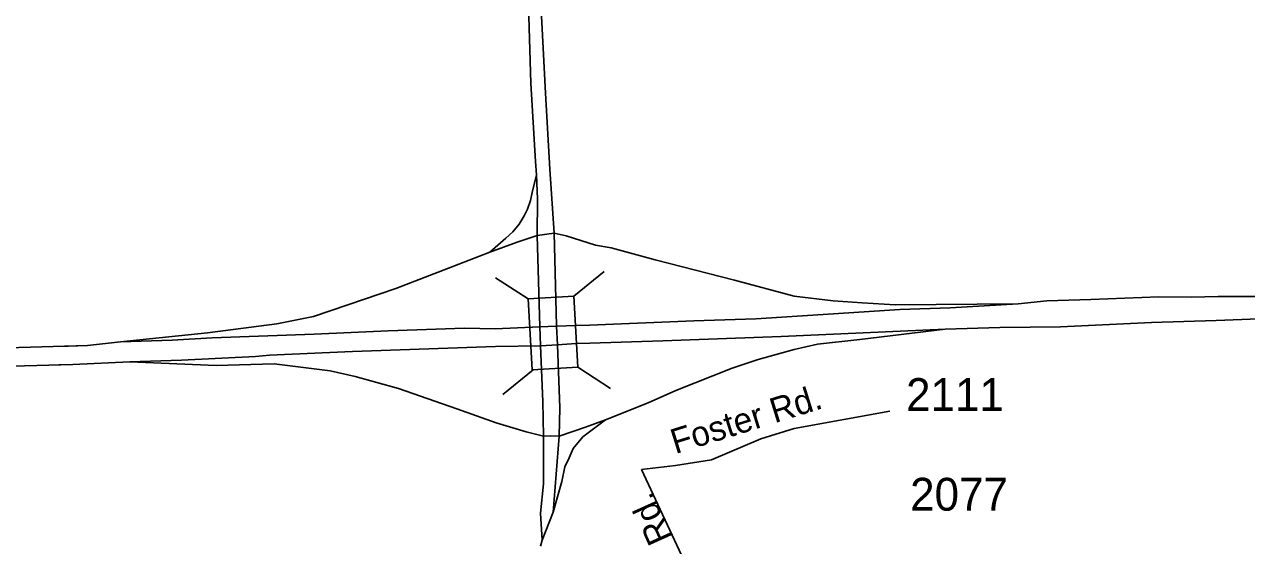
# Model space of a CAD drawing. Extents: x 1364363 to 1407445, y 538563 to 573342.
# Drawn here: x 1392969 to 1397619, y 553876 to 555859 of the extents above; entities that cross this region are included whole.
import ezdxf

# ---------------------------------------------------------------- set-up
doc = ezdxf.new("R2010")
doc.units = 0
for name, color, linetype in [('Exist Road Primary Interstate Divided Center Attributed', 7, 'Continuous'), ('Exist Road Primary Interstate Ramp 1 Lane Attributed', 7, 'Continuous'), ('Exist Road Primary NC Attributed', 7, 'Continuous'), ('Exist Road Primary NC Divided Attributed', 7, 'Continuous'), ('Exist Road Primary NC Structure Standard Bridge CELL', 7, 'Continuous'), ('Exist Road Secondary Type 51 Attributed', 7, 'Continuous'), ('Exist Road Secondary Type 51 Label', 7, 'Continuous'), ('Exist Road Secondary Type 51 Number Label', 7, 'Continuous')]:
    doc.layers.add(name, color=color, linetype=linetype)

msp = doc.modelspace()

# ---------------------------------------------------------------- linework, layer by layer
at = {"layer": 'Exist Road Primary Interstate Divided Center Attributed'}
for points in [[(1393334.1, 554650.6), (1393208.8, 554636.6), (1392904.1, 554627.7), (1392654.8, 554617.2), (1392079.2, 554588.8), (1391717.5, 554575.4), (1391295.9, 554565), (1391159.1, 554570.5), (1391050.8, 554573.9), (1390956.2, 554582), (1390800.3, 554606.6), (1390596.7, 554648.1), (1390451, 554686.9), (1390252.5, 554747.1), (1390046.2, 554841.3), (1389929.6, 554904)], [(1398849.6, 554881.8), (1398622.7, 554863.5), (1398365.7, 554860.9), (1398224.1, 554853.5), (1397774.1, 554823.3), (1397511, 554823.3), (1397410.2, 554820.3), (1397285.4, 554822.5), (1397027.4, 554812.3), (1396859.2, 554806.8), (1396750.2, 554795.2)], [(1398849.6, 554881.8), (1398622.7, 554863.5), (1398365.7, 554860.9), (1398224.1, 554853.5), (1397774.1, 554823.3), (1397511, 554823.3), (1397410.2, 554820.3), (1397285.4, 554822.5), (1397027.4, 554812.3), (1396859.2, 554806.8), (1396750.2, 554795.2)], [(1389950.7, 554820.1), (1390107.1, 554752.5), (1390152.2, 554734.9), (1390279.4, 554676.9), (1390414.8, 554627.7), (1390541, 554585.9), (1390641, 554563.5), (1390764.2, 554535.1), (1390924.2, 554508.2), (1391099.7, 554491.8), (1391285.9, 554488.8), (1391495.9, 554494.8), (1391787.6, 554511.9), (1392073.5, 554525), (1392329.8, 554531.6), (1392830.9, 554556.2), (1393152.9, 554564.5), (1393369.8, 554575.1)], [(1396472.2, 554699.3), (1396679.9, 554705.3), (1396910.8, 554708.3), (1397203.9, 554721.7), (1397257.8, 554724.7), (1397504, 554732.2), (1397924.9, 554748.6), (1398253, 554772.1), (1398871.8, 554808)], [(1396472.2, 554699.3), (1396679.9, 554705.3), (1396910.8, 554708.3), (1397203.9, 554721.7), (1397257.8, 554724.7), (1397504, 554732.2), (1397924.9, 554748.6), (1398253, 554772.1), (1398871.8, 554808)], [(1396750.2, 554795.2), (1396491.5, 554780.3), (1396300.1, 554774.1), (1396008.2, 554754.6), (1395752.7, 554738.1), (1395515.7, 554730.7), (1395119.8, 554714.9), (1395067.1, 554712.8), (1394994.2, 554710.5)], [(1396750.2, 554795.2), (1396491.5, 554780.3), (1396300.1, 554774.1), (1396008.2, 554754.6), (1395752.7, 554738.1), (1395515.7, 554730.7), (1395119.8, 554714.9), (1395067.1, 554712.8), (1394994.2, 554710.5)], [(1394929.9, 554708.5), (1394759.8, 554700.9), (1394644.1, 554702.6), (1394353.4, 554693.1), (1394071.4, 554680.1), (1393683.3, 554665.8), (1393530.8, 554657.6), (1393334.1, 554650.6)], [(1394929.9, 554708.5), (1394759.8, 554700.9), (1394644.1, 554702.6), (1394353.4, 554693.1), (1394071.4, 554680.1), (1393683.3, 554665.8), (1393530.8, 554657.6), (1393334.1, 554650.6)], [(1394994.2, 554710.5), (1394929.9, 554708.5)], [(1394994.2, 554710.5), (1394929.9, 554708.5)], [(1394997.1, 554640), (1395068.6, 554644.1), (1395121, 554645.8), (1395398, 554654.5), (1395848.9, 554671), (1396472.2, 554699.3)], [(1394997.1, 554640), (1395068.6, 554644.1), (1395121, 554645.8), (1395398, 554654.5), (1395848.9, 554671), (1396472.2, 554699.3)], [(1393334.1, 554650.6), (1393208.8, 554636.6), (1393099.7, 554633.4)], [(1393369.8, 554575.1), (1393566.9, 554580.9), (1393847.9, 554595.7), (1393901.6, 554599.8), (1394217.8, 554614.7), (1394761.4, 554633.5), (1394932.8, 554636.3)], [(1393369.8, 554575.1), (1393566.9, 554580.9), (1393847.9, 554595.7), (1393901.6, 554599.8), (1394217.8, 554614.7), (1394761.4, 554633.5), (1394932.8, 554636.3)], [(1394932.8, 554636.3), (1394997.1, 554640)], [(1394932.8, 554636.3), (1394997.1, 554640)], [(1393099.7, 554563.1), (1393152.9, 554564.5), (1393369.8, 554575.1)]]:
    msp.add_lwpolyline(points, dxfattribs=at)
at = {"layer": 'Exist Road Primary Interstate Ramp 1 Lane Attributed'}
for points in [[(1394917.5, 555286.5), (1394901.5, 555219.7), (1394894.3, 555188.9), (1394883.2, 555155.6), (1394870.7, 555130.1), (1394851.4, 555098.7), (1394827.3, 555069.8), (1394800.3, 555045.2), (1394739.5, 554992.2)], [(1394917.5, 555286.5), (1394901.5, 555219.7), (1394894.3, 555188.9), (1394883.2, 555155.6), (1394870.7, 555130.1), (1394851.4, 555098.7), (1394827.3, 555069.8), (1394800.3, 555045.2), (1394739.5, 554992.2)], [(1394920.3, 555056), (1394844.1, 555029.8), (1394739.5, 554992.2)], [(1394920.3, 555056), (1394844.1, 555029.8), (1394739.5, 554992.2)], [(1394984.7, 555064.2), (1394920.3, 555056)], [(1394984.7, 555064.2), (1394920.3, 555056)], [(1396750.2, 554795.2), (1396282.4, 554791.2), (1396157.1, 554799.3), (1396046.8, 554806.8), (1395898.3, 554825.1), (1395671.3, 554885.2), (1395368.6, 554962.8), (1395201.8, 555008.4), (1395142.5, 555019.3), (1395030.1, 555054.5), (1394984.7, 555064.2)], [(1396750.2, 554795.2), (1396282.4, 554791.2), (1396157.1, 554799.3), (1396046.8, 554806.8), (1395898.3, 554825.1), (1395671.3, 554885.2), (1395368.6, 554962.8), (1395201.8, 555008.4), (1395142.5, 555019.3), (1395030.1, 555054.5), (1394984.7, 555064.2)], [(1394739.5, 554992.2), (1394582.8, 554930.8), (1394382.6, 554853.8), (1394199.5, 554791.7), (1394068.5, 554747.5), (1393929.1, 554719.2), (1393666.3, 554684.9), (1393334.1, 554650.6)], [(1394739.5, 554992.2), (1394582.8, 554930.8), (1394382.6, 554853.8), (1394199.5, 554791.7), (1394068.5, 554747.5), (1393929.1, 554719.2), (1393666.3, 554684.9), (1393334.1, 554650.6)], [(1396472.2, 554699.3), (1396147.6, 554659.5), (1395986.2, 554642), (1395898.4, 554622.2), (1395761.5, 554584.1), (1395662.1, 554550.7), (1395448.3, 554466.2), (1395342.7, 554418.6), (1395180.4, 554354)], [(1396472.2, 554699.3), (1396147.6, 554659.5), (1395986.2, 554642), (1395898.4, 554622.2), (1395761.5, 554584.1), (1395662.1, 554550.7), (1395448.3, 554466.2), (1395342.7, 554418.6), (1395180.4, 554354)], [(1393369.8, 554575.1), (1393698.8, 554561.4), (1393919.5, 554566.9), (1394131.9, 554540.9), (1394227.9, 554518.9), (1394392.1, 554474), (1394614.3, 554396.3), (1394763.7, 554343), (1394878.6, 554308), (1394944.6, 554292.3)], [(1393369.8, 554575.1), (1393698.8, 554561.4), (1393919.5, 554566.9), (1394131.9, 554540.9), (1394227.9, 554518.9), (1394392.1, 554474), (1394614.3, 554396.3), (1394763.7, 554343), (1394878.6, 554308), (1394944.6, 554292.3)], [(1394981.6, 554002.8), (1395014.5, 554119.4), (1395025.4, 554175.4), (1395041.8, 554210.1), (1395057, 554245.6), (1395094.1, 554289.5), (1395180.4, 554354)], [(1394981.6, 554002.8), (1395014.5, 554119.4), (1395025.4, 554175.4), (1395041.8, 554210.1), (1395057, 554245.6), (1395094.1, 554289.5), (1395180.4, 554354)], [(1395003.6, 554292.3), (1395103.9, 554326.3), (1395180.4, 554354)], [(1395003.6, 554292.3), (1395103.9, 554326.3), (1395180.4, 554354)], [(1394944.6, 554292.3), (1394970.7, 554293.6), (1395003.6, 554292.3)], [(1394944.6, 554292.3), (1394970.7, 554293.6), (1395003.6, 554292.3)]]:
    msp.add_lwpolyline(points, dxfattribs=at)
at = {"layer": 'Exist Road Primary NC Attributed'}
msp.add_lwpolyline([(1394932.4, 553873.7), (1394939.6, 553896.5)], dxfattribs=at)
msp.add_lwpolyline([(1394932.4, 553873.7), (1394939.6, 553896.5)], dxfattribs=at)
at = {"layer": 'Exist Road Primary NC Divided Attributed'}
msp.add_line((1394997.1, 554640), (1394994.2, 554710.5), dxfattribs=at)
msp.add_line((1394997.1, 554640), (1394994.2, 554710.5), dxfattribs=at)
for points in [[(1395047.9, 559619.8), (1395020, 559494.5), (1394962.8, 559261.6), (1394883.8, 558946.9), (1394756.5, 558444.8), (1394733.8, 558324.4), (1394731.8, 558313), (1394712.9, 558171.7), (1394701.3, 558051.8), (1394699.3, 558002.1), (1394695.2, 557919.7), (1394695.2, 557805.9), (1394702.7, 557583.9), (1394710.8, 557502.8), (1394725.1, 557353), (1394755.8, 557087.5), (1394778.9, 556872.5), (1394812.8, 556641), (1394846.6, 556384.2), (1394865.9, 556194.6), (1394887.4, 555930.4), (1394895.9, 555634.7), (1394913.4, 555337.2), (1394917.5, 555286.5)], [(1395047.9, 559619.8), (1395020, 559494.5), (1394962.8, 559261.6), (1394883.8, 558946.9), (1394756.5, 558444.8), (1394733.8, 558324.4), (1394731.8, 558313), (1394712.9, 558171.7), (1394701.3, 558051.8), (1394699.3, 558002.1), (1394695.2, 557919.7), (1394695.2, 557805.9), (1394702.7, 557583.9), (1394710.8, 557502.8), (1394725.1, 557353), (1394755.8, 557087.5), (1394778.9, 556872.5), (1394812.8, 556641), (1394846.6, 556384.2), (1394865.9, 556194.6), (1394887.4, 555930.4), (1394895.9, 555634.7), (1394913.4, 555337.2), (1394917.5, 555286.5)], [(1394984.7, 555064.2), (1394968.2, 555307.8), (1394951.3, 555597.1), (1394951.3, 555597.4), (1394934.4, 555939.3), (1394923.6, 556093.1), (1394897.4, 556340.9), (1394879.7, 556533.5), (1394847.4, 556778.4), (1394800.5, 557126.3), (1394755.1, 557433.3), (1394742.8, 557538.4), (1394732, 557728), (1394733.3, 557888.3), (1394740.5, 558016.1), (1394746.6, 558131.1), (1394762, 558256.5), (1394805.9, 558474.5), (1394841.3, 558667.1), (1394897.4, 558883.6), (1394957.4, 559118), (1395087.5, 559625.6)], [(1394984.7, 555064.2), (1394968.2, 555307.8), (1394951.3, 555597.1), (1394951.3, 555597.4), (1394934.4, 555939.3), (1394923.6, 556093.1), (1394897.4, 556340.9), (1394879.7, 556533.5), (1394847.4, 556778.4), (1394800.5, 557126.3), (1394755.1, 557433.3), (1394742.8, 557538.4), (1394732, 557728), (1394733.3, 557888.3), (1394740.5, 558016.1), (1394746.6, 558131.1), (1394762, 558256.5), (1394805.9, 558474.5), (1394841.3, 558667.1), (1394897.4, 558883.6), (1394957.4, 559118), (1395087.5, 559625.6)], [(1394917.5, 555286.5), (1394921.7, 555193.2), (1394920.3, 555056)], [(1394917.5, 555286.5), (1394921.7, 555193.2), (1394920.3, 555056)], [(1394920.3, 555056), (1394929.9, 554708.5)], [(1394920.3, 555056), (1394929.9, 554708.5)], [(1394994.2, 554710.5), (1394992.1, 554764.3), (1394984.7, 555064.2)], [(1394994.2, 554710.5), (1394992.1, 554764.3), (1394984.7, 555064.2)], [(1394929.9, 554708.5), (1394931.3, 554673.2), (1394932.8, 554636.3)], [(1394929.9, 554708.5), (1394931.3, 554673.2), (1394932.8, 554636.3)], [(1394932.8, 554636.3), (1394941.3, 554423.9), (1394944.6, 554292.3)], [(1394932.8, 554636.3), (1394941.3, 554423.9), (1394944.6, 554292.3)], [(1395003.6, 554292.3), (1395006.7, 554400), (1394997.1, 554640)], [(1395003.6, 554292.3), (1395006.7, 554400), (1394997.1, 554640)], [(1394944.6, 554292.3), (1394944.6, 554111.2), (1394932.3, 553998.7), (1394939.6, 553896.5)], [(1394944.6, 554292.3), (1394944.6, 554111.2), (1394932.3, 553998.7), (1394939.6, 553896.5)], [(1394981.6, 554002.8), (1395003.6, 554292.3)], [(1394981.6, 554002.8), (1395003.6, 554292.3)], [(1394939.6, 553896.5), (1394981.6, 554002.8)], [(1394939.6, 553896.5), (1394981.6, 554002.8)]]:
    msp.add_lwpolyline(points, dxfattribs=at)
at = {"layer": 'Exist Road Primary NC Structure Standard Bridge CELL'}
for p, q in [((1395174.7, 554917.9), (1395059.8, 554824.1)), ((1395174.7, 554917.9), (1395059.8, 554824.1)), ((1394761.6, 554894.5), (1394886.3, 554814.2)), ((1394761.6, 554894.5), (1394886.3, 554814.2)), ((1394904.7, 554544.7), (1394789.8, 554450.8)), ((1394904.7, 554544.7), (1394789.8, 554450.8)), ((1395074.2, 554554.3), (1395199, 554474)), ((1395074.2, 554554.3), (1395199, 554474))]:
    msp.add_line(p, q, dxfattribs=at)
msp.add_lwpolyline([(1395059.8, 554824.1), (1395075, 554554.4), (1394901.6, 554544.5), (1394886.3, 554814.2)], close=True, dxfattribs=at)
msp.add_lwpolyline([(1395059.8, 554824.1), (1395075, 554554.4), (1394901.6, 554544.5), (1394886.3, 554814.2)], close=True, dxfattribs=at)
at = {"layer": 'Exist Road Secondary Type 51 Attributed'}
for points in [[(1395316.5, 554165.1), (1395446.9, 554180.2), (1395583.4, 554201.5), (1395771.3, 554281.6), (1395898.1, 554321), (1396261.6, 554387.5)], [(1395316.5, 554165.1), (1395446.9, 554180.2), (1395583.4, 554201.5), (1395771.3, 554281.6), (1395898.1, 554321), (1396261.6, 554387.5)], [(1395316.5, 554165.1), (1395487.1, 553801.3)], [(1395316.5, 554165.1), (1395487.1, 553801.3)]]:
    msp.add_lwpolyline(points, dxfattribs=at)

# ---------------------------------------------------------------- texts
at = {"layer": 'Exist Road Secondary Type 51 Label'}
for s, rotation, p in [('Foster Rd.', 17.2812, (1395445.8, 554223.3)), ('Foster Rd.', 17.2812, (1395445.8, 554223.3)), ('Rd.', 114.2995, (1395435.5, 553905.5)), ('Rd.', 114.2995, (1395435.5, 553905.5))]:
    msp.add_text(s, height=95, rotation=rotation, dxfattribs=at).set_placement(p)
at = {"layer": 'Exist Road Secondary Type 51 Number Label'}
for s, p in [('2111', (1396323.9, 554387.8)), ('2111', (1396323.9, 554387.8)), ('2077', (1396339.3, 554008.5)), ('2077', (1396339.3, 554008.5))]:
    msp.add_text(s, height=125, dxfattribs=at).set_placement(p)

doc.saveas('drawing.dxf')
